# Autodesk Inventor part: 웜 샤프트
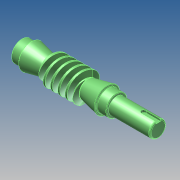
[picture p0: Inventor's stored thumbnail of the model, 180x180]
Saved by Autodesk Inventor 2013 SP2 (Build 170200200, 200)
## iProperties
Created: 2025-06
Part Number: 웜 샤프트
Material: Generic
Document SubType Name: Modeling
Designer: i
Density: 1 g/cm^3
Author: i
변환 표준: STEP AP214IS
전처리기: Build: 200, Release: 2013 SP2 Update 6 - Date: Thu 07/17/2014
전송 단위: 밀리미터
불확실성: 0.01
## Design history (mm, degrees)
node "웜 샤프트1"
body "Solid1"
node "기준1"
